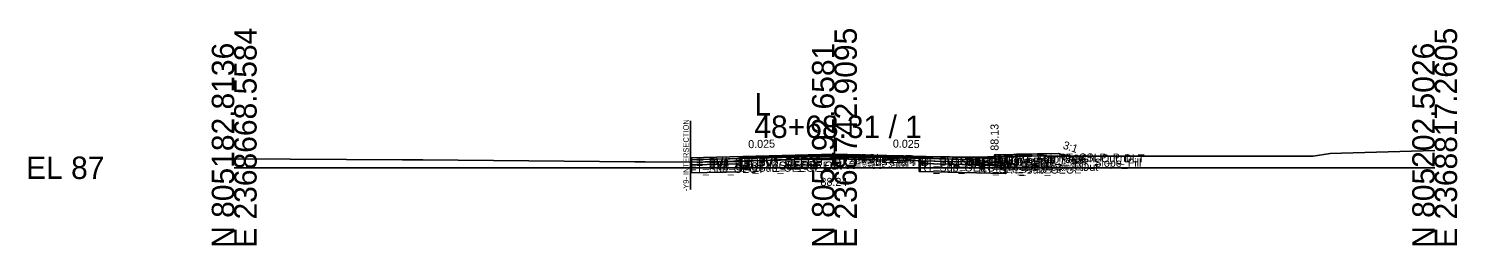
# Model space of a CAD drawing. Extents: x -26 to 8153, y -10 to 9520.
# Drawn here: x 3974.3 to 4152.8, y 5990.3 to 6017.4 of the extents above; entities that cross this region are included whole.
import ezdxf

# ---------------------------------------------------------------- set-up
doc = ezdxf.new("R2010")
doc.units = 0
for name, color, linetype in [('Exist CMT Pavement', 7, 'Continuous'), ('Exist Cross Section Cell', 7, 'Continuous'), ('Exist XS Center Line Elevation Label', 7, 'Continuous'), ('Exist XS Ground Line', 7, 'Continuous'), ('Prop CMT Conc Surface', 7, 'Continuous'), ('Prop CMT Concrete Structures', 7, 'Continuous'), ('Prop CMT Pvmt Course 1', 7, 'Continuous'), ('Prop CMT Pvmt Course 1 CG', 7, 'Continuous'), ('Prop CMT Pvmt Course 1 Wedge', 7, 'Continuous'), ('Prop CMT Pvmt Course 2', 7, 'Continuous'), ('Prop CMT Pvmt Course 2 Wedge', 7, 'Continuous'), ('Prop CMT Pvmt Course 3', 7, 'Continuous'), ('Prop CMT Pvmt Course 3 Wedge', 7, 'Continuous'), ('Prop CMT Pvmt Surface', 7, 'Continuous'), ('Prop CMT Pvmt Wedge Surface 1', 7, 'Continuous'), ('Prop CMT Pvmt Wedge Surface 2', 7, 'Continuous'), ('Prop CMT Pvmt Wedge Surface 3', 7, 'Continuous'), ('Prop CMT Shallow Undercut', 7, 'Continuous'), ('Prop CMT Shallow Undercut Boundary', 7, 'Continuous'), ('Prop CMT Shear Line', 7, 'Continuous'), ('Prop CMT Slope Grass', 7, 'Continuous'), ('Prop CMT Subgrade Earthwork', 7, 'Continuous'), ('Prop XS Earthwork Shape', 7, 'Continuous'), ('Prop XS Hydro Elevations', 7, 'Continuous'), ('Prop XS SE Text', 7, 'Continuous'), ('Prop XS Side Slope Text', 7, 'Continuous'), ('Prop XS Subgrade Earthwork', 7, 'Continuous'), ('Scratch_Level_2', 7, 'Continuous'), ('Scratch_Level_6', 7, 'Continuous')]:
    doc.layers.add(name, color=color, linetype=linetype)

msp = doc.modelspace()

# ---------------------------------------------------------------- linework, layer by layer
at = {"layer": 'Exist CMT Pavement'}
for p, q in [((4060.45, 6000.7), (4074.47, 6001.23)), ((4074.47, 6001.23), (4074.82, 6001.24)), ((4074.82, 6001.24), (4085.59, 6001.37))]:
    msp.add_line(p, q, dxfattribs=at)
at = {"layer": 'Exist Cross Section Cell'}
for p, q in [((4075, 6000), (4075, 6006.52)), ((4000, 6000), (4075, 6000)), ((4075, 6000), (4150, 6000))]:
    msp.add_line(p, q, dxfattribs=at)
at = {"layer": 'Exist XS Ground Line'}
for p, q in [((4000, 6001.13), (4021.04, 6001.01)), ((4021.04, 6001.01), (4023.57, 6000.99)), ((4023.57, 6000.99), (4050.04, 6000.74)), ((4050.04, 6000.74), (4051.35, 6000.74)), ((4051.35, 6000.74), (4060.45, 6000.7)), ((4060.45, 6000.7), (4074.47, 6001.23)), ((4074.47, 6001.23), (4074.82, 6001.24)), ((4074.82, 6001.24), (4085.59, 6001.37)), ((4085.59, 6001.37), (4093.37, 6001.33)), ((4093.37, 6001.33), (4094.14, 6001.35)), ((4094.14, 6001.35), (4096.2, 6001.4)), ((4096.2, 6001.4), (4101.82, 6001.47)), ((4101.82, 6001.47), (4102.42, 6001.43)), ((4102.42, 6001.43), (4134.8, 6001.44)), ((4134.8, 6001.44), (4136.95, 6001.76)), ((4136.95, 6001.76), (4138.35, 6001.81)), ((4138.35, 6001.81), (4150, 6002.17))]:
    msp.add_line(p, q, dxfattribs=at)
at = {"layer": 'Prop CMT Conc Surface'}
for points in [[(4093, 6001.26), (4095, 6001.13)], [(4095, 6001.13), (4095, 6001.63), (4095.5, 6001.63)]]:
    msp.add_lwpolyline(points, dxfattribs=at)
at = {"layer": 'Prop CMT Concrete Structures'}
for points in [[(4093, 6001.26), (4095, 6001.13), (4095, 6001.63), (4095.5, 6001.63)], [(4095.5, 6001.63), (4095.5, 6000.62), (4093, 6000.68)], [(4093, 6000.68), (4093, 6001.26)]]:
    msp.add_lwpolyline(points, dxfattribs=at)
at = {"layer": 'Prop CMT Pvmt Course 1'}
for points in [[(4075, 6001.71), (4057, 6001.26)], [(4057, 6001.26), (4057, 6001.01)], [(4057, 6001.01), (4063.2, 6001.17)], [(4063.2, 6001.29), (4075, 6001.59)], [(4063.2, 6001.17), (4063.2, 6001.29)], [(4075, 6001.46), (4075, 6001.71)], [(4075, 6001.71), (4093, 6001.26)], [(4075, 6001.46), (4075, 6001.71)], [(4075, 6001.59), (4075, 6001.46), (4075, 6001.46)], [(4085.6, 6001.32), (4075, 6001.59)], [(4075, 6001.59), (4075, 6001.46), (4075, 6001.46)], [(4085.6, 6001.2), (4085.6, 6001.37)], [(4093, 6001.01), (4085.6, 6001.2)], [(4093, 6001.26), (4093, 6001.01)]]:
    msp.add_lwpolyline(points, dxfattribs=at)
at = {"layer": 'Prop CMT Pvmt Course 1 CG'}
for points in [[(4093, 6000.68), (4096, 6000.6), (4096.34, 6000.27)], [(4093, 6000.35), (4093, 6000.68)], [(4096.34, 6000.27), (4093, 6000.35)]]:
    msp.add_lwpolyline(points, dxfattribs=at)
at = {"layer": 'Prop CMT Pvmt Course 1 Wedge'}
for points in [[(4075, 6001.59), (4063.2, 6001.29)], [(4075, 6001.59), (4085.6, 6001.32)]]:
    msp.add_lwpolyline(points, dxfattribs=at)
at = {"layer": 'Prop CMT Pvmt Course 2'}
for points in [[(4063.2, 6001.17), (4057, 6001.01)], [(4057, 6001.01), (4057, 6000.68)], [(4057, 6000.68), (4063.2, 6000.84)], [(4063.2, 6000.84), (4063.2, 6001.17)], [(4085.6, 6000.87), (4085.6, 6001.2)], [(4085.6, 6001.2), (4093, 6001.01)], [(4093, 6000.68), (4085.6, 6000.87)], [(4093, 6001.01), (4093, 6000.68)]]:
    msp.add_lwpolyline(points, dxfattribs=at)
at = {"layer": 'Prop CMT Pvmt Course 2 Wedge'}
for points in [[(4075, 6001.46), (4063.2, 6001.17)], [(4075, 6001.46), (4085.6, 6001.2)]]:
    msp.add_lwpolyline(points, dxfattribs=at)
at = {"layer": 'Prop CMT Pvmt Course 3'}
for points in [[(4063.2, 6000.84), (4057, 6000.68)], [(4057, 6000.68), (4057, 6000.35)], [(4057, 6000.35), (4063.2, 6000.5)], [(4063.2, 6000.5), (4063.2, 6000.84)], [(4085.6, 6000.87), (4093, 6000.68)], [(4085.6, 6000.53), (4085.6, 6000.87)], [(4093, 6000.35), (4085.6, 6000.53)], [(4093, 6000.68), (4093, 6000.35)]]:
    msp.add_lwpolyline(points, dxfattribs=at)
at = {"layer": 'Prop CMT Pvmt Course 3 Wedge'}
for points in [[(4075, 6001.13), (4063.2, 6000.84)], [(4075, 6001.13), (4085.6, 6000.87)]]:
    msp.add_lwpolyline(points, dxfattribs=at)
at = {"layer": 'Prop CMT Pvmt Surface'}
for points in [[(4075, 6001.71), (4057, 6001.26), (4057, 6000.72)], [(4075, 6001.71), (4093, 6001.26)]]:
    msp.add_lwpolyline(points, dxfattribs=at)
at = {"layer": 'Prop CMT Pvmt Wedge Surface 1'}
for points in [[(4057, 6001.01), (4057, 6001.26)], [(4063.2, 6001.17), (4057, 6001.01)], [(4075, 6001.59), (4063.2, 6001.29)], [(4063.2, 6001.29), (4063.2, 6001.17)], [(4075, 6001.59), (4085.6, 6001.32)], [(4085.6, 6001.32), (4085.6, 6001.2)], [(4085.6, 6001.2), (4093, 6001.01)], [(4093, 6001.01), (4093, 6001.26)]]:
    msp.add_lwpolyline(points, dxfattribs=at)
at = {"layer": 'Prop CMT Pvmt Wedge Surface 2'}
for points in [[(4075, 6001.46), (4057, 6001.01)], [(4057, 6001.01), (4057, 6001.26)], [(4075, 6001.46), (4093, 6001.01)], [(4093, 6001.01), (4093, 6001.26)]]:
    msp.add_lwpolyline(points, dxfattribs=at)
at = {"layer": 'Prop CMT Pvmt Wedge Surface 3'}
for points in [[(4057, 6000.68), (4057, 6001.26)], [(4075, 6001.13), (4057, 6000.68)], [(4075, 6001.13), (4093, 6000.68)], [(4093, 6000.68), (4093, 6001.26)]]:
    msp.add_lwpolyline(points, dxfattribs=at)
at = {"layer": 'Prop CMT Shallow Undercut'}
for p, q in [((4063.2, 6000.5), (4057, 6000.35)), ((4063.2, 5999.5), (4063.2, 6000.5)), ((4085.6, 6000.53), (4085.6, 5999.53)), ((4096.34, 6000.27), (4085.6, 6000.53)), ((4057, 6000.35), (4057, 5999.35)), ((4057, 5999.35), (4063.2, 5999.5)), ((4085.6, 5999.53), (4096.34, 5999.27)), ((4096.34, 5999.27), (4096.34, 6000.27))]:
    msp.add_line(p, q, dxfattribs=at)
at = {"layer": 'Prop CMT Shallow Undercut Boundary'}
for p, q in [((4063.2, 6000.5), (4063.2, 5999.5)), ((4085.6, 6000.53), (4085.6, 5999.53)), ((4057, 6000.35), (4057, 5999.35)), ((4057, 5999.35), (4063.2, 5999.5)), ((4085.6, 5999.53), (4096.34, 5999.27)), ((4096.34, 6000.27), (4096.34, 5999.27))]:
    msp.add_line(p, q, dxfattribs=at)
at = {"layer": 'Prop CMT Shear Line'}
msp.add_line((4057, 5997.27), (4057, 6005.84), dxfattribs=at)
at = {"layer": 'Prop CMT Slope Grass'}
msp.add_lwpolyline([(4095.5, 6001.63), (4103, 6001.78), (4104.05, 6001.43)], dxfattribs=at)
at = {"layer": 'Prop CMT Subgrade Earthwork'}
for points in [[(4063.2, 6000.5), (4057, 6000.35)], [(4063.2, 6000.5), (4063.2, 6000.81)], [(4085.6, 6000.53), (4085.6, 6001.37)], [(4085.6, 6000.53), (4093, 6000.35)], [(4093, 6000.35), (4096.34, 6000.27), (4097.75, 6001.68)]]:
    msp.add_lwpolyline(points, dxfattribs=at)
at = {"layer": 'Prop XS Earthwork Shape'}
for points in [[(4057, 5999.35), (4063.2, 5999.5), (4063.2, 6000.5), (4057, 6000.35)], [(4095, 6001.13), (4095, 6001.37), (4096.2, 6001.4), (4097.49, 6001.41), (4096.34, 6000.27), (4093, 6000.35), (4085.6, 6000.53), (4085.6, 6001.37), (4089.46, 6001.35), (4093, 6001.26)], [(4085.6, 5999.53), (4096.34, 5999.27), (4096.34, 6000.27), (4093, 6000.35), (4085.6, 6000.53)], [(4095, 6001.13), (4095, 6001.37), (4094.14, 6001.35), (4093.37, 6001.33), (4089.46, 6001.35), (4093, 6001.26)], [(4101.82, 6001.47), (4102.42, 6001.43), (4104.05, 6001.43), (4103, 6001.78), (4097.75, 6001.68), (4097.49, 6001.41)]]:
    msp.add_lwpolyline(points, close=True, dxfattribs=at)
at = {"layer": 'Prop XS Subgrade Earthwork'}
for p, q in [((4057, 6000.35), (4063.2, 6000.5)), ((4096.34, 6000.27), (4085.6, 6000.53))]:
    msp.add_line(p, q, dxfattribs=at)
at = {"layer": 'Scratch_Level_6'}
for p, q in [((4063.2, 6000.5), (4057, 6000.35)), ((4063.2, 5999.5), (4063.2, 6000.5)), ((4085.6, 6000.53), (4085.6, 5999.53)), ((4096.34, 6000.27), (4085.6, 6000.53)), ((4057, 6000.35), (4057, 5999.35)), ((4057, 5999.35), (4063.2, 5999.5)), ((4085.6, 5999.53), (4096.34, 5999.27)), ((4096.34, 5999.27), (4096.34, 6000.27))]:
    msp.add_line(p, q, dxfattribs=at)

# ---------------------------------------------------------------- texts
at = {"layer": 'Exist Cross Section Cell'}
for s, p in [('E 2368668.5584', (4002.8, 5990)), ('E 2368742.9095', (4077.8, 5990)), ('E 2368817.2605', (4152.8, 5990)), ('N 805182.8136', (4000, 5990)), ('N 805192.6581', (4075, 5990)), ('N 805202.5026', (4150, 5990))]:
    msp.add_text(s, height=2.8, rotation=90, dxfattribs=at).set_placement(p)
for s, p in [('L', (4065, 6006.52)), ('48+68.31 / 1', (4065, 6003.72)), ('EL 87', (3974, 5998.6))]:
    msp.add_text(s, height=2.8, dxfattribs=at).set_placement(p)
at = {"layer": 'Exist XS Center Line Elevation Label'}
msp.add_text('88.24', height=1, dxfattribs=at).set_placement((4073.26, 5997.74))
at = {"layer": 'Prop CMT Shear Line'}
msp.add_text('-Y9- INTERSECTION', height=0.7, rotation=90, dxfattribs=at).set_placement((4056.8, 5997.06))
at = {"layer": 'Prop XS Hydro Elevations'}
msp.add_text('88.13', height=1, rotation=90, dxfattribs=at).set_placement((4095.5, 6002.13))
at = {"layer": 'Prop XS SE Text'}
for rotation, p in [(1.4321, (4064.24, 6002.44)), (358.5679, (4082.29, 6002.53))]:
    msp.add_text('0.025', height=1, rotation=rotation, dxfattribs=at).set_placement(p)
at = {"layer": 'Prop XS Side Slope Text'}
msp.add_text('3:1', height=1, rotation=341.5651, dxfattribs=at).set_placement((4103.46, 6002.42))
at = {"layer": 'Scratch_Level_2'}
for s, p in [('LT_PV1_OEOT', (4057, 6000.26)), ('LT_PV2_OEOT', (4057, 6000.01)), ('LT_PV3_OEOT', (4057, 5999.68)), ('LT_PV1_OEEOP', (4063.2, 6000.29)), ('LT_PV2_OEEOP', (4063.2, 6000.17)), ('LT_PV3_OEEOP', (4063.2, 5999.84)), ('LT_PV_OEEOP_EG', (4063.2, 5999.78)), ('LT_Sub_OEEOP', (4063.2, 5999.5)), ('LT_PV_Sub_Tie_Out', (4063.21, 5999.78)), ('PV1_PGL', (4075, 6000.71)), ('RT_PV1_IEEOP', (4075, 6000.59)), ('LT_PV1_IEEOP', (4075, 6000.59)), ('RT_PV2_IEEOP', (4075, 6000.46)), ('LT_PV2_IEEOP', (4075, 6000.46)), ('PV2_PGL', (4075, 6000.46)), ('RT_PV_IEEOP_EG', (4075, 6000.24)), ('LT_PV_IEEOP_EG', (4075, 6000.24)), ('RT_PV3_IEEOP', (4075, 6000.13)), ('LT_PV3_IEEOP', (4075, 6000.13)), ('RT_PV_Sub_Tie_Out', (4085.58, 6000.37)), ('RT_PV_OEEOP_EG', (4085.6, 6000.37)), ('RT_PV1_OEEOP', (4085.6, 6000.32)), ('RT_PV2_OEEOP', (4085.6, 6000.2)), ('RT_PV3_OEEOP', (4085.6, 5999.87)), ('RT_Sub_OEEOP', (4085.6, 5999.53)), ('RT_PV1_OEOT', (4093, 6000.26)), ('RT_PV2_OEOT', (4093, 6000.01)), ('RT_PV3_OEOT', (4093, 5999.68)), ('RT_CG_Bot_IE', (4093, 5999.68)), ('RT_CG_Top_Face', (4095, 6000.63)), ('RT_CG_Top_Gut', (4095, 6000.13)), ('RT_CG_Top_BOC', (4095.5, 6000.63)), ('RT_CG_Bot_BOC', (4095.5, 5999.62)), ('RT_CG1_Shelf_Out', (4096, 5999.6)), ('RT_Sub_Trench_Out_DLT', (4097.75, 6000.68)), ('RT_CSLP_Pnt', (4103, 6000.78)), ('RT_Slope_Fill', (4104.95, 6000.13)), ('LT_Sub_OEOT', (4057, 5999.35)), ('RT_Sub_OEOT', (4093, 5999.35)), ('RT_Sub_OEOP', (4096.34, 5999.27))]:
    msp.add_text(s, height=1, dxfattribs=at).set_placement(p)

doc.saveas('drawing.dxf')
